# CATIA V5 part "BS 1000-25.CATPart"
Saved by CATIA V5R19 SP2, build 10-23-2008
Part number: BS 1000-25
Bounding box of the stored display mesh (mm): x -24.865 to 24.865, y -24.997 to 24.997, z 0 to 88
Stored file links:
  C:\Users\Bora\Desktop\3D Katı model\BS serisi\BS 1000\BS 1000-25.CATPart
  C:\Program Files\Dassault Systemes\B19\intel_a\reffiles\standard\MetricThickPitch.txt
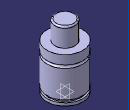
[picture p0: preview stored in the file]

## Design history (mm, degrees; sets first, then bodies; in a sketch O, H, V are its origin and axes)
Body1 (main body)
  Sketch1 on yz-plane, origin (0, 0, 0), H (0, 1, 0), V (0, 0, 1)
    point P1 (14, 86)
    point P4 (25, 49.5)
    point P5 (25, 45.5)
    point P9 (25, 49.5)
    point P10 (25, 45.5)
    point P11 (14, 86)
    point P13 (22.5, 4)
    point P15 (22.5, 4)
    line L1 (14, 86) -> (14, 62)
    line L2 (25, 62) -> (25, 49.5)
    line L3 (25, 45.5) -> (25, 7.5)
    line L4 (25, 4) -> (25, 0)
    arc A1 centre (25, 47.5) radius 2 from (25, 49.5) to (25, 45.5) ccw
    arc A2 centre (12, 86) radius 2 from (14, 86) to (12, 88) ccw
    line L5 (22.5, 7.5) -> (22.5, 4)
    line L6 (12, 88) -> (0, 88)
    point P16 (0, 88)
    line L7 (14, 62) -> (25, 62)
    line L8 (0, 0) -> (25, 0)
    line L9 (22.5, 7.5) -> (25, 7.5)
    line L10 (22.5, 4) -> (25, 4)
    coincidence: P16 V, P1 P11, P4 P9, P5 P10, P13 P15
    tangency: L6 A2
    horizontal: L7 H, L8 H, L9 H, L10 H
  Shaft1: profile Sketch1, axis Sketch1.V, angle 360
  Sketch2 on face of Shaft1 from Sketch1.L8, origin (0, 0, 0), H (1, 0, 0), V (0, -1, 0)
    point P1 (10, 0)
    distance P1 V = 10
  Hole1: placed by Sketch2, at (10, 0, 0) direction (0, 0, 1), diameter 6.647, depth 6, threaded "M8", thread diameter 8, thread depth 6, pitch 1.25
  CircPattern1: of Hole1, instances 2, angular step 180, axis from xy-plane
